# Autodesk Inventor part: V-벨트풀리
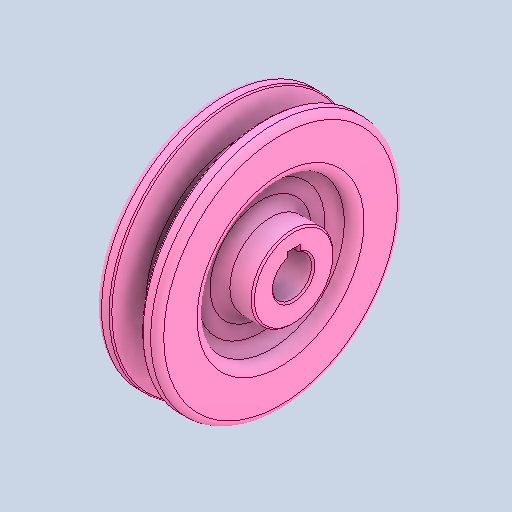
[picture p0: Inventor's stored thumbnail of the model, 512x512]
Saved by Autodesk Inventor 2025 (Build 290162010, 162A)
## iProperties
Created: 2024-07
Part Number: V-벨트풀리
Material: 강철, 탄소
Document SubType Name: Modeling
Designer: Admin
Density: 7.87 g/cm^3
Appearance: 기본값
Author: jhkim
Sending System: Autodesk Inventor 2025
Preprocessor: ST-DEVELOPER v20
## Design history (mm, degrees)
feature "솔리드1"
node "솔리드2"
